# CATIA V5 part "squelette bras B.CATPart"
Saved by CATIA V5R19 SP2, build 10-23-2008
Part number: squelette bras B
Publications: "Plan de symetrie"
Bounding box of the stored display mesh (mm): x -100 to 100, y 0 to 20, z 0 to 250
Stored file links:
  G:\EU_thinkMotion\CFAO_2010\MMS_groupe3\MMS_groupe3\A reprendre\mmugnier\Systeme_Cric_Y\Systeme_Cric_Y\squelette bras B.CATPart
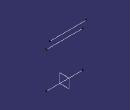
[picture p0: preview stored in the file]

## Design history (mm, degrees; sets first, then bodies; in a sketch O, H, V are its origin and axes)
Parameters
  `Longueur 2 4` = 200 mm
  `Longueur 4 5` = 50 mm
  `Decalage axe 5` = 20 mm
Set1
  Line1 "Axe 2": type Normal, RefPoint {point type Coord, X 0, Y 0, Z 0}, RefSkin yz-plane, Start -100, End 100
  Line2 "Axe 4": type Normal, RefPoint {point type Coord, X 0, Y 0, Z 200 {= `Longueur 2 4`}}, RefSkin yz-plane, Start -100, End 100
  Line3 "Axe 5": type Normal, RefPoint {point type Coord, X 0, Y 20 {= `Decalage axe 5`}, Z 250 {= `Longueur 2 4` +`Longueur 4 5`}}, RefSkin yz-plane, Start -100, End 100
Body1 (main body)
